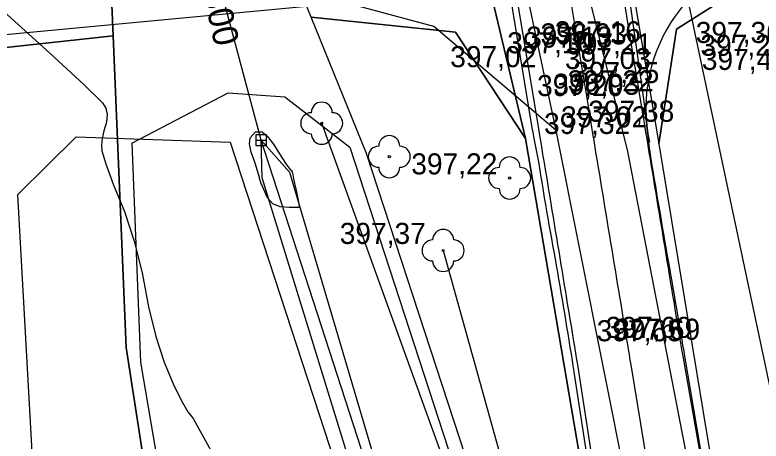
# Model space of a CAD drawing. Extents: x -574342 to -508101, y -1143544 to -1123894.
# Drawn here: x -508450.68 to -508415.22, y -1143279.46 to -1143259.23 of the extents above; entities that cross this region are included whole.
import ezdxf

# ---------------------------------------------------------------- set-up
doc = ezdxf.new("R2010")
doc.units = 0
for name, color, linetype in [('01_PARCELY_NAVRH_PC', 7, 'Continuous'), ('01_PARCELY_NAVRH_VHO', 7, 'Continuous'), ('01_PARCELY_NAVRH_ŽP', 7, 'Continuous'), ('05_VHO_V_TOK_STAV', 7, 'Continuous'), ('1000', 7, 'Continuous'), ('15', 7, 'Continuous'), ('21', 7, 'Continuous'), ('37', 7, 'Continuous'), ('42', 7, 'Continuous'), ('51', 7, 'Continuous'), ('52', 7, 'Continuous'), ('54', 7, 'Continuous'), ('55', 7, 'Continuous'), ('60', 7, 'Continuous'), ('cesty', 7, 'Continuous'), ('Level 255', 7, 'Continuous'), ('VRST VEDL', 7, 'Continuous')]:
    doc.layers.add(name, color=color, linetype=linetype)

msp = doc.modelspace()

# ---------------------------------------------------------------- linework, layer by layer
at = {"layer": '01_PARCELY_NAVRH_PC'}
for points in [[(-508451.57, -1143168.14), (-508437.66, -1143207.58), (-508425.52, -1143241.92), (-508422.7, -1143249.88), (-508420.08, -1143265.35), (-508416.18, -1143288.91), (-508414.34, -1143296.2), (-508410.3, -1143304.94), (-508406.96, -1143310.33), (-508402.64, -1143313.55), (-508394.5, -1143317.14), (-508397.53, -1143325.93), (-508402.47, -1143323.55), (-508407.39, -1143320.93), (-508414.82, -1143312.69), (-508418.17, -1143303.49), (-508422.28, -1143289.33), (-508426.41, -1143265.09), (-508431, -1143245.85), (-508431.86, -1143242.81), (-508432.73, -1143240.34), (-508445.99, -1143206.42), (-508454.33, -1143183.49)], [(-508109.096, -1143172.158), (-508188.91, -1143212.74), (-508197.69, -1143215.86), (-508325.49, -1143244.3), (-508415.56, -1143252.78), (-508417.38, -1143252.95), (-508420.04, -1143252.1), (-508422.7, -1143249.88), (-508420.08, -1143265.35), (-508419.24, -1143259.91), (-508414.23, -1143256.72), (-508401.25, -1143255.47), (-508381.42, -1143253.61), (-508325.37, -1143248.48), (-508191.76, -1143218.68), (-508109.096, -1143176.822)]]:
    msp.add_lwpolyline(points, dxfattribs=at)
for points in [[(-508431, -1143245.85), (-508426.41, -1143265.09), (-508429.75, -1143260.04), (-508436.6, -1143259.34), (-508438.17, -1143255.47), (-508435.43, -1143255.05), (-508431.73, -1143252.13)], [(-508446.21, -1143255.76), (-508469.74, -1143257.73), (-508480.76, -1143258.08), (-508496.39, -1143258.35), (-508520.28, -1143255.11), (-508526.55, -1143254.9), (-508531.16, -1143250.06), (-508524.26, -1143263.08), (-508521.01, -1143259.29), (-508514.56, -1143259.91), (-508493.5, -1143263.3), (-508475.11, -1143263.39), (-508446.02, -1143260.22)]]:
    msp.add_lwpolyline(points, close=True, dxfattribs=at)
at = {"layer": '01_PARCELY_NAVRH_VHO'}
msp.add_lwpolyline([(-508469.74, -1143257.73), (-508446.21, -1143255.76), (-508446.02, -1143260.22), (-508445.4, -1143275.01), (-508441.9, -1143297.61), (-508434.31, -1143320.59), (-508432.21, -1143324.29), (-508414.59, -1143317.71), (-508420.1, -1143305.91), (-508426.78, -1143287.77), (-508433.97, -1143265.8), (-508436.6, -1143259.34), (-508438.17, -1143255.47), (-508441.16, -1143248.09), (-508442.91, -1143245.61), (-508437.61, -1143243.22), (-508434.06, -1143242.54), (-508431.86, -1143242.81), (-508432.73, -1143240.34), (-508433.72, -1143240.11), (-508438.05, -1143241.09), (-508444.11, -1143244.2), (-508446.56, -1143243.12), (-508452.58, -1143244.39)], dxfattribs=at)
at = {"layer": '01_PARCELY_NAVRH_ŽP'}
for points in [[(-508355.53, -1143335.68), (-508361.58, -1143328.14), (-508368.91, -1143322.84), (-508376.72, -1143318.72), (-508388.31, -1143315.9), (-508393.87, -1143311.09), (-508396.73, -1143306.67), (-508414.23, -1143256.72), (-508419.24, -1143259.91), (-508420.08, -1143265.35), (-508416.18, -1143288.91), (-508414.34, -1143296.2), (-508410.3, -1143304.94), (-508406.96, -1143310.33), (-508402.64, -1143313.55), (-508394.5, -1143317.14), (-508377.05, -1143323.29), (-508363.05, -1143330.55), (-508352.96, -1143343.32)], [(-508425.23, -1143400.39), (-508448.26, -1143343.08), (-508432.21, -1143324.29), (-508434.31, -1143320.59), (-508441.9, -1143297.61), (-508445.4, -1143275.01), (-508446.02, -1143260.22), (-508475.11, -1143263.39), (-508493.5, -1143263.3), (-508514.56, -1143259.91), (-508521.01, -1143259.29), (-508524.26, -1143263.08), (-508519.86, -1143267.33), (-508511.25, -1143285.64), (-508506.89, -1143298.29), (-508504.21, -1143312.1), (-508498.26, -1143372.94), (-508491.36, -1143454.58)]]:
    msp.add_lwpolyline(points, dxfattribs=at)
msp.add_lwpolyline([(-508436.6, -1143259.34), (-508429.75, -1143260.04), (-508426.41, -1143265.09), (-508422.28, -1143289.33), (-508418.17, -1143303.49), (-508414.82, -1143312.69), (-508407.39, -1143320.93), (-508402.47, -1143323.55), (-508412.73, -1143323), (-508414.59, -1143317.71), (-508420.1, -1143305.91), (-508426.78, -1143287.77), (-508433.97, -1143265.8)], close=True, dxfattribs=at)
at = {"layer": '05_VHO_V_TOK_STAV'}
msp.add_lwpolyline([(-508396.743, -1143399.678), (-508414.306, -1143332.655), (-508430.208, -1143292.193), (-508438.98, -1143265.17), (-508442.91, -1143250.47), (-508445.36, -1143246.6), (-508447.49, -1143245.57), (-508453.89, -1143245.84)], dxfattribs=at)
at = {"layer": '1000'}
for points in [[(-508421.696, -1143256.911), (-508420.73, -1143263.798), (-508420.728, -1143263.818), (-508420.696, -1143264.124), (-508420.662, -1143264.45), (-508420.628, -1143264.775), (-508420.593, -1143265.101), (-508420.559, -1143265.427), (-508420.515, -1143265.751), (-508420.462, -1143266.074), (-508420.408, -1143266.396), (-508420.353, -1143266.719), (-508420.299, -1143267.041), (-508420.244, -1143267.364), (-508420.189, -1143267.686), (-508420.135, -1143268.008), (-508420.08, -1143268.331), (-508420.024, -1143268.653), (-508419.969, -1143268.975), (-508419.914, -1143269.298), (-508419.859, -1143269.62), (-508419.803, -1143269.942), (-508419.748, -1143270.265), (-508419.692, -1143270.587), (-508419.636, -1143270.909), (-508419.58, -1143271.231), (-508419.524, -1143271.554), (-508419.468, -1143271.876), (-508419.412, -1143272.198), (-508419.355, -1143272.52), (-508419.299, -1143272.842), (-508419.242, -1143273.164), (-508419.186, -1143273.486), (-508419.129, -1143273.809), (-508419.076, -1143274.131), (-508419.024, -1143274.454), (-508418.97, -1143274.777), (-508418.947, -1143274.916), (-508418.914, -1143275.099), (-508418.857, -1143275.421), (-508417.442, -1143283.716)], [(-508422.001, -1143256.961), (-508420.867, -1143263.821), (-508420.864, -1143263.84), (-508420.813, -1143264.143), (-508420.76, -1143264.466), (-508420.707, -1143264.788), (-508420.653, -1143265.111), (-508420.6, -1143265.434), (-508420.547, -1143265.756), (-508420.493, -1143266.079), (-508420.44, -1143266.402), (-508420.387, -1143266.724), (-508420.333, -1143267.047), (-508420.28, -1143267.37), (-508420.227, -1143267.692), (-508420.173, -1143268.015), (-508420.12, -1143268.337), (-508420.067, -1143268.66), (-508420.013, -1143268.983), (-508419.96, -1143269.305), (-508419.906, -1143269.628), (-508419.853, -1143269.951), (-508419.8, -1143270.273), (-508419.746, -1143270.596), (-508419.693, -1143270.919), (-508419.64, -1143271.241), (-508419.586, -1143271.564), (-508419.533, -1143271.887), (-508419.48, -1143272.209), (-508419.426, -1143272.532), (-508419.373, -1143272.854), (-508419.32, -1143273.177), (-508419.266, -1143273.5), (-508419.213, -1143273.822), (-508419.159, -1143274.145), (-508419.106, -1143274.468), (-508419.053, -1143274.79), (-508419.03, -1143274.929), (-508418.998, -1143275.113), (-508418.941, -1143275.435), (-508417.485, -1143283.723)], [(-508427.224, -1143257.825), (-508426.094, -1143264.685), (-508426.09, -1143264.704), (-508426.033, -1143265.006), (-508425.972, -1143265.328), (-508425.911, -1143265.649), (-508425.85, -1143265.971), (-508425.79, -1143266.292), (-508425.734, -1143266.614), (-508425.682, -1143266.937), (-508425.63, -1143267.26), (-508425.578, -1143267.583), (-508425.525, -1143267.906), (-508425.473, -1143268.228), (-508425.415, -1143268.55), (-508425.358, -1143268.872), (-508425.3, -1143269.194), (-508425.242, -1143269.516), (-508425.185, -1143269.838), (-508425.127, -1143270.16), (-508425.07, -1143270.482), (-508425.013, -1143270.804), (-508424.956, -1143271.126), (-508424.899, -1143271.448), (-508424.842, -1143271.77), (-508424.785, -1143272.092), (-508424.73, -1143272.414), (-508424.676, -1143272.737), (-508424.623, -1143273.06), (-508424.57, -1143273.382), (-508424.516, -1143273.705), (-508424.463, -1143274.028), (-508424.41, -1143274.35), (-508424.358, -1143274.673), (-508424.305, -1143274.996), (-508424.252, -1143275.319), (-508424.2, -1143275.641), (-508424.177, -1143275.781), (-508424.149, -1143275.965), (-508424.1, -1143276.288), (-508422.826, -1143284.607)], [(-508426.934, -1143257.777), (-508425.8, -1143264.636), (-508425.797, -1143264.656), (-508425.746, -1143264.959), (-508425.693, -1143265.282), (-508425.64, -1143265.604), (-508425.586, -1143265.927), (-508425.533, -1143266.249), (-508425.48, -1143266.572), (-508425.426, -1143266.895), (-508425.373, -1143267.217), (-508425.32, -1143267.54), (-508425.266, -1143267.863), (-508425.213, -1143268.185), (-508425.16, -1143268.508), (-508425.106, -1143268.831), (-508425.053, -1143269.153), (-508425, -1143269.476), (-508424.946, -1143269.799), (-508424.893, -1143270.121), (-508424.839, -1143270.444), (-508424.786, -1143270.766), (-508424.733, -1143271.089), (-508424.679, -1143271.412), (-508424.626, -1143271.734), (-508424.573, -1143272.057), (-508424.519, -1143272.38), (-508424.466, -1143272.702), (-508424.413, -1143273.025), (-508424.359, -1143273.348), (-508424.306, -1143273.67), (-508424.253, -1143273.993), (-508424.199, -1143274.315), (-508424.146, -1143274.638), (-508424.092, -1143274.961), (-508424.039, -1143275.283), (-508423.986, -1143275.606), (-508423.963, -1143275.745), (-508423.934, -1143275.929), (-508423.884, -1143276.252), (-508422.594, -1143284.568)]]:
    msp.add_lwpolyline(points, dxfattribs=at)
at = {"layer": '21'}
msp.add_lwpolyline([(-508424.468, -1143257.369), (-508423.333, -1143264.228), (-508423.33, -1143264.248), (-508423.28, -1143264.551), (-508423.227, -1143264.874), (-508423.173, -1143265.196), (-508423.12, -1143265.519), (-508423.067, -1143265.842), (-508423.013, -1143266.164), (-508422.96, -1143266.487), (-508422.906, -1143266.81), (-508422.853, -1143267.132), (-508422.8, -1143267.455), (-508422.746, -1143267.777), (-508422.693, -1143268.1), (-508422.64, -1143268.423), (-508422.586, -1143268.745), (-508422.533, -1143269.068), (-508422.48, -1143269.391), (-508422.426, -1143269.713), (-508422.373, -1143270.036), (-508422.32, -1143270.359), (-508422.266, -1143270.681), (-508422.213, -1143271.004), (-508422.16, -1143271.326), (-508422.106, -1143271.649), (-508422.053, -1143271.972), (-508421.999, -1143272.294), (-508421.946, -1143272.617), (-508421.893, -1143272.94), (-508421.839, -1143273.262), (-508421.786, -1143273.585), (-508421.733, -1143273.908), (-508421.679, -1143274.23), (-508421.626, -1143274.553), (-508421.573, -1143274.876), (-508421.519, -1143275.198), (-508421.496, -1143275.337), (-508421.466, -1143275.521), (-508421.413, -1143275.843), (-508420.04, -1143284.146)], dxfattribs=at)
at = {"layer": '37'}
for points in [[(-508473.82, -1143129.8), (-508468.34, -1143141.31), (-508458.53, -1143158.76), (-508453.13, -1143170.86), (-508439.96, -1143210.5), (-508427.56, -1143241.73), (-508421.57, -1143265.72), (-508416.35, -1143292.6), (-508412.42, -1143304.7), (-508408.82, -1143311.83)], [(-508473.82, -1143129.8), (-508468.34, -1143141.31), (-508458.53, -1143158.76), (-508453.13, -1143170.86), (-508439.96, -1143210.5), (-508427.56, -1143241.73), (-508421.57, -1143265.72), (-508416.35, -1143292.6), (-508412.42, -1143304.7), (-508408.82, -1143311.83)], [(-508408.82, -1143311.83), (-508404.37, -1143317.04), (-508398.21, -1143321.18), (-508393.66, -1143322.44), (-508393.79, -1143324.58), (-508400.56, -1143323.11), (-508406.32, -1143319.06), (-508411.41, -1143313.16), (-508415.31, -1143305.9), (-508419.33, -1143292.88), (-508424.96, -1143264.72), (-508428.49, -1143248.11), (-508430.27, -1143242.09), (-508442.28, -1143211.48), (-508455.59, -1143171.17), (-508460.82, -1143160.05), (-508470.5, -1143142.85)], [(-508408.82, -1143311.83), (-508404.37, -1143317.04), (-508398.21, -1143321.18), (-508393.66, -1143322.44), (-508393.79, -1143324.58), (-508400.56, -1143323.11), (-508406.32, -1143319.06), (-508411.41, -1143313.16), (-508415.31, -1143305.9), (-508419.33, -1143292.88), (-508424.96, -1143264.72), (-508428.49, -1143248.11), (-508430.27, -1143242.09), (-508442.28, -1143211.48), (-508455.59, -1143171.17), (-508460.82, -1143160.05), (-508470.5, -1143142.85)]]:
    msp.add_lwpolyline(points, dxfattribs=at)
at = {"layer": '42'}
for points in [[(-508447.77, -1143265.01), (-508450.56, -1143267.77), (-508449.78, -1143281.67), (-508439.59, -1143305.77), (-508430.42, -1143328.77), (-508427.01, -1143330.22), (-508422.43, -1143319.83)], [(-508447.77, -1143265.01), (-508450.56, -1143267.77), (-508449.78, -1143281.67), (-508439.59, -1143305.77), (-508430.42, -1143328.77), (-508427.01, -1143330.22), (-508422.43, -1143319.83)], [(-508447.77, -1143265.01), (-508440.46, -1143265.27), (-508432.82, -1143288.61), (-508427.18, -1143305.48), (-508422.43, -1143319.83)], [(-508447.77, -1143265.01), (-508440.46, -1143265.27), (-508432.82, -1143288.61), (-508427.18, -1143305.48), (-508422.43, -1143319.83)]]:
    msp.add_lwpolyline(points, dxfattribs=at)
at = {"layer": '51'}
msp.add_lwpolyline([(-508420.91, -1143320.11), (-508425.97, -1143305.4), (-508432.32, -1143288.39), (-508438.93, -1143266.96), (-508438.98, -1143265.17), (-508437.64, -1143266.69), (-508431.24, -1143288.3), (-508424.98, -1143304.96), (-508418.78, -1143319.62)], dxfattribs=at)
msp.add_lwpolyline([(-508420.91, -1143320.11), (-508425.97, -1143305.4), (-508432.32, -1143288.39), (-508438.93, -1143266.96), (-508438.98, -1143265.17), (-508437.64, -1143266.69), (-508431.24, -1143288.3), (-508424.98, -1143304.96), (-508418.78, -1143319.62)], dxfattribs=at)
at = {"layer": '52'}
msp.add_line((-508439.23, -1143265.17), (-508438.73, -1143265.17), dxfattribs=at)
msp.add_lwpolyline([(-508439.23, -1143265.42), (-508438.73, -1143265.42), (-508438.73, -1143264.92), (-508439.23, -1143264.92)], close=True, dxfattribs=at)
at = {"layer": '54'}
for centre in [(-508436.1, -1143264.37), (-508432.89, -1143265.96), (-508427.17, -1143266.97), (-508430.33, -1143270.41)]:
    msp.add_circle(centre, 0.05, dxfattribs=at)
for centre, start, end in [((-508436.1, -1143263.87), 0, 180), ((-508436.6, -1143264.37), 90, 270), ((-508435.6, -1143264.37), 270, 90), ((-508436.1, -1143264.87), 180, 0), ((-508432.89, -1143265.46), 0, 180), ((-508433.39, -1143265.96), 90, 270), ((-508432.39, -1143265.96), 270, 90), ((-508427.17, -1143266.47), 0, 180), ((-508432.89, -1143266.46), 180, 0), ((-508427.67, -1143266.97), 90, 270), ((-508426.67, -1143266.97), 270, 90), ((-508427.17, -1143267.47), 180, 0), ((-508430.33, -1143269.91), 0, 180), ((-508430.83, -1143270.41), 90, 270), ((-508429.83, -1143270.41), 270, 90), ((-508430.33, -1143270.91), 180, 0)]:
    msp.add_arc(centre, 0.5, start, end, dxfattribs=at)
at = {"layer": '55'}
for points in [[(-508410.24, -1143298.34), (-508420.04, -1143252.1), (-508438.58, -1143205.02)], [(-508410.24, -1143298.34), (-508420.04, -1143252.1), (-508438.58, -1143205.02)], [(-508424.96, -1143264.72), (-508430.77, -1143259.78), (-508434.96, -1143258.66), (-508472.39, -1143262.17), (-508495.8, -1143262.63)], [(-508424.96, -1143264.72), (-508430.77, -1143259.78), (-508434.96, -1143258.66), (-508472.39, -1143262.17), (-508495.8, -1143262.63)], [(-508408, -1143322.07), (-508412.54, -1143325.06), (-508424.05, -1143297.62), (-508436.1, -1143264.37)], [(-508408, -1143322.07), (-508412.54, -1143325.06), (-508424.05, -1143297.62), (-508436.1, -1143264.37)], [(-508430.33, -1143270.41), (-508426.06, -1143285.7), (-508418.81, -1143305.71)], [(-508430.33, -1143270.41), (-508426.06, -1143285.7), (-508418.81, -1143305.71)]]:
    msp.add_lwpolyline(points, dxfattribs=at)
at = {"layer": '60'}
for points in [[(-508445.13, -1143265.32), (-508440.54, -1143262.92), (-508437.86, -1143263.12), (-508434.77, -1143265.51), (-508427.96, -1143286.38), (-508421.22, -1143304.15), (-508412.75, -1143323.05)], [(-508445.13, -1143265.32), (-508440.54, -1143262.92), (-508437.86, -1143263.12), (-508434.77, -1143265.51), (-508427.96, -1143286.38), (-508421.22, -1143304.15), (-508412.75, -1143323.05)], [(-508445.13, -1143265.32), (-508444.71, -1143275.72), (-508440.65, -1143299.58), (-508433.69, -1143320.63), (-508429.23, -1143329.11)], [(-508445.13, -1143265.32), (-508444.71, -1143275.72), (-508440.65, -1143299.58), (-508433.69, -1143320.63), (-508429.23, -1143329.11)]]:
    msp.add_lwpolyline(points, dxfattribs=at)
at = {"layer": 'cesty'}
msp.add_arc((-508413.198, -1143263.648), 7.5, 95.3361, 192.4584, dxfattribs=at)
at = {"layer": 'VRST VEDL'}
msp.add_lwpolyline([(-508451.371, -1143258.92), (-508449.024, -1143261.038), (-508447.407, -1143262.533), (-508446.521, -1143263.405), (-508446.366, -1143263.654), (-508446.305, -1143263.959), (-508446.337, -1143264.318), (-508446.463, -1143264.733), (-508446.541, -1143265.1), (-508446.572, -1143265.418), (-508446.555, -1143265.686), (-508446.367, -1143266.301), (-508446.007, -1143267.26), (-508445.477, -1143268.565), (-508445.022, -1143269.971), (-508444.642, -1143271.479), (-508444.338, -1143273.087), (-508443.99, -1143274.5), (-508443.596, -1143275.716), (-508443.157, -1143276.736), (-508442.781, -1143277.52), (-508442.468, -1143278.069), (-508442.217, -1143278.382), (-508441.29, -1143280.052)], dxfattribs=at)
msp.add_lwpolyline([(-508439.248, -1143264.783), (-508438.928, -1143264.783), (-508438.697, -1143264.978), (-508438.395, -1143265.369), (-508438.022, -1143265.956), (-508437.758, -1143266.357), (-508437.601, -1143266.573), (-508437.554, -1143266.604), (-508437.511, -1143266.683), (-508437.473, -1143266.811), (-508437.44, -1143266.987), (-508437.39, -1143267.234), (-508437.323, -1143267.551), (-508437.239, -1143267.939), (-508437.191, -1143268.204), (-508437.178, -1143268.347), (-508437.201, -1143268.366), (-508437.36, -1143268.372), (-508437.653, -1143268.364), (-508438.082, -1143268.342), (-508438.425, -1143268.193), (-508438.684, -1143267.918), (-508438.857, -1143267.515), (-508438.976, -1143267.225), (-508439.042, -1143267.049), (-508439.054, -1143266.987), (-508439.064, -1143266.929), (-508439.074, -1143266.877), (-508439.083, -1143266.829), (-508439.149, -1143266.624), (-508439.272, -1143266.259), (-508439.454, -1143265.737), (-508439.532, -1143265.341), (-508439.506, -1143265.071)], close=True, dxfattribs=at)

# ---------------------------------------------------------------- texts
at = {"layer": '15'}
msp.add_text('DN 800', height=1.2, rotation=282.2963, dxfattribs=at).set_placement((-508442.336, -1143255.463))
msp.add_text('DN 800', height=1.2, rotation=282.2963, dxfattribs=at).set_placement((-508442.336, -1143255.463))
at = {"layer": 'Level 255'}
for s, p in [('397,13', (-508426.385, -1143260.78)), ('396,93', (-508425.705, -1143260.63)), ('397,16', (-508425.025, -1143260.53)), ('397,36', (-508418.325, -1143260.56)), ('397,10', (-508427.285, -1143261.05)), ('397,21', (-508424.485, -1143261.1)), ('397,26', (-508418.105, -1143261.17)), ('397,02', (-508429.995, -1143261.71)), ('397,03', (-508424.545, -1143261.8)), ('397,42', (-508418.035, -1143261.84)), ('397,25', (-508424.145, -1143262.46)), ('397,22', (-508424.415, -1143262.86)), ('397,20', (-508425.865, -1143263.08)), ('396,93', (-508425.095, -1143263.02)), ('397,38', (-508423.435, -1143264.3)), ('397,02', (-508424.725, -1143264.57)), ('397,32', (-508425.535, -1143264.88)), ('397,22', (-508431.845, -1143266.8)), ('397,37', (-508435.245, -1143270.1)), ('397,60', (-508422.605, -1143274.56)), ('397,65', (-508423.035, -1143274.72)), ('397,69', (-508422.205, -1143274.65))]:
    msp.add_text(s, height=1, dxfattribs=at).set_placement(p)

doc.saveas('drawing.dxf')
